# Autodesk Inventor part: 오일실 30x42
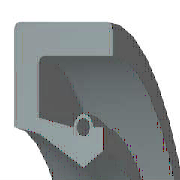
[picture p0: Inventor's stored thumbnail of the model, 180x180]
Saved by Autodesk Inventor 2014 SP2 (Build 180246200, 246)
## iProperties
IsCustomPart: 0
Company: 한국ATC센터
Created: 2009-02
Part Number: 오일실 30x42
Material: 고무
Description: 오일-실
Document SubType Name: Modeling
Standard: KS B 2804
Designer: KYOUNG IL JANG
Standards Organization: KS
Language: ko-KR
Size Designation: S - 30 42 8
Categories: <MemberInstance><Categories><Category DisplayName="샤프트 부품" InternalName="7f7aeb1f-a693-4053-b835-cee3144e0d98" Mnemonic="SHFT"><Category DisplayName="실링" Intern
Density: 0.93 g/cm^3
Appearance: 고무 - 검은색 - 버전 1.1
Author: KYOUNG IL JANG
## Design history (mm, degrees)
revolve "본체" stored, may be unused: angle "d17" = 90 deg
revolve "스프링1" stored, may be unused: angle "d18" = 90 deg
body "Solid1"
sketch "스케치1"
  geometry: L1 (0, 21)-(8, 21); L2 (8, 21)-(8, 19.75); L3 (8, 19.75)-(1.75, 19.75); L4 (0, 21)-(0, 17.1); L5 (0, 17.1)-(1.75, 16.75); L6 (1.75, 16.75)-(4.9, 15); L7 (4.9, 15)-(0, 15); L8 (6.3, 15.875)-(6.3, 17.1); L9 (0, 0)-(9.586, 0) reference; L10 (4.9, 15)-(6.3, 15.875); L11 (0, 18)-(0, -3) reference; L12 (-1.917, 0)-(11.503, 0) reference; L13 (4.2, 17.1)-(1.75, 17.59); L14 (1.75, 17.59)-(1.75, 19.75); L15 (6.3, 17.1)-(5.6, 17.1); C1 r 0.455 at (4.9, 17.1); A1 r 0.7 centre (4.9, 17.1) between (5.6, 17.1) and (4.2, 17.1)
  constraints: 26 end point, 5 horizontal alignment, 4 perpendicular, 2 centre point, 2 collinear, 2 horizontal, 2 parallel, 2 point on circle, 2 point on line, 2 vertical alignment, 1 coincident
  dimensions: "d0" = 42 diameter of L1 L9 (= SD2); "d1" = 31.75 diameter of L8.start L9 (= ABDM); "d2" = 1.25 distance of L1.end L2.end (computed from SD); "d3" = 0.91 diameter of C1 (= SPDI); "d4" = 1.4 diameter of A1 (= SPDA); "d5" = 30 diameter of L6.end L9 (= NND); "d6" = 33.5 diameter of L5.end L9 (= TKDM); "d7" = 34.2 diameter of L4.end L9 (= HLDM); "d8" = 4.9 distance from line of C1.centre L4 (= SPDST); "d9" = 6.3 distance between parallel lines of L8 L4 (= SDI); "d10" = 8 distance between parallel lines of L2 L4 (= SWDT); "d12" = 1.75 distance between parallel lines of L14 L4 (= SD)
fillet "모깎기1" dims "d11" = 0.4 (= RR)
other parameters: "SD2" = 42 [user parameter; used in 1 equation term], "SWDT" = 8 [user parameter; used in 1 equation term], "RR" = 0.4 [user parameter; used in 1 equation term], "SD" = 1.75 [user parameter; used in 2 equation terms], "NND" = 30 [user parameter; used in 1 equation term], "SPDA" = 1.4 [user parameter; used in 1 equation term], "SPDI" = 0.91 [user parameter; used in 1 equation term], "TKDM" = 33.5 [user parameter; used in 1 equation term], "HLDM" = 34.2 [user parameter; used in 1 equation term], "ABDM" = 31.75 [user parameter; used in 1 equation term], "SDI" = 6.3 [user parameter; used in 1 equation term], "SPDST" = 4.9 [user parameter; used in 1 equation term], "d13" = 0, "d14" = 0, "d15" = 0, "LAB" = 0.35 [user parameter]
